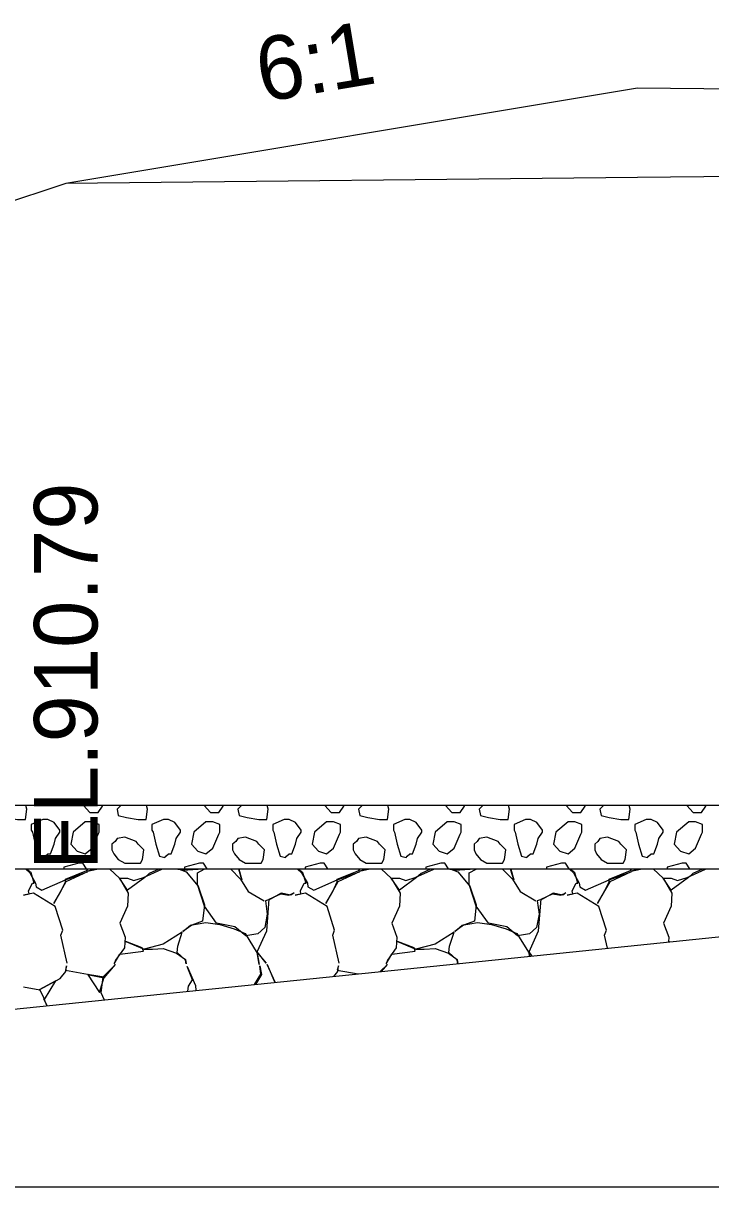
# Model space of a CAD drawing. Extents: x -26 to 4781, y -31 to 24738.
# Drawn here: x 2268.33 to 2279.16, y 7000 to 7018.31 of the extents above; entities that cross this region are included whole.
import ezdxf

# ---------------------------------------------------------------- set-up
doc = ezdxf.new("R2010")
doc.units = 0
for name, color, linetype in [('DESIGN - SHEET - Light Grid', 7, 'Continuous'), ('DESIGN - TRANSPORTATION - Proposed Layout Patterning', 7, 'Continuous'), ('DESIGN - TYPICAL - Finished Grade and Subgrade', 7, 'Continuous'), ('DESIGN - TYPICAL - Finished Grade Slopes Text', 7, 'Continuous'), ('DESIGN - TYPICAL - Subgrade Tie Text', 7, 'Continuous'), ('GEOTECHNICAL – SCRATCH – Level 1', 7, 'Continuous'), ('SURVEY - GROUND - Top of Ground', 7, 'Continuous')]:
    doc.layers.add(name, color=color, linetype=linetype)

msp = doc.modelspace()

# ---------------------------------------------------------------- linework, layer by layer
at = {"layer": 'DESIGN - SHEET - Light Grid'}
msp.add_line((2000, 7000), (2300, 7000), dxfattribs=at)
at = {"layer": 'DESIGN - TRANSPORTATION - Proposed Layout Patterning'}
for p, q in [((2269.308, 7005.741), (2269.118, 7005.581)), ((2271.208, 7005.741), (2271.018, 7005.581)), ((2273.108, 7005.741), (2272.918, 7005.581)), ((2275.008, 7005.741), (2274.818, 7005.581)), ((2276.908, 7005.741), (2276.718, 7005.581)), ((2278.808, 7005.741), (2278.618, 7005.581)), ((2268.458, 7005.611), (2268.478, 7005.581)), ((2270.358, 7005.611), (2270.378, 7005.581)), ((2272.258, 7005.611), (2272.278, 7005.581)), ((2274.158, 7005.611), (2274.178, 7005.581)), ((2276.058, 7005.611), (2276.078, 7005.581)), ((2277.958, 7005.611), (2277.978, 7005.581))]:
    msp.add_line(p, q, dxfattribs=at)
for points in [[(2267.967, 7006), (2267.908, 7005.941), (2267.928, 7005.841), (2268.058, 7005.811), (2268.238, 7005.781), (2268.368, 7005.781), (2268.388, 7005.941), (2268.371, 7006)], [(2269.279, 7006), (2269.378, 7005.891), (2269.508, 7005.891), (2269.578, 7005.991), (2269.582, 7006)], [(2269.867, 7006), (2269.808, 7005.941), (2269.828, 7005.841), (2269.958, 7005.811), (2270.138, 7005.781), (2270.268, 7005.781), (2270.288, 7005.941), (2270.271, 7006)], [(2271.179, 7006), (2271.278, 7005.891), (2271.408, 7005.891), (2271.478, 7005.991), (2271.482, 7006)], [(2271.767, 7006), (2271.708, 7005.941), (2271.728, 7005.841), (2271.858, 7005.811), (2272.038, 7005.781), (2272.168, 7005.781), (2272.188, 7005.941), (2272.171, 7006)], [(2273.079, 7006), (2273.178, 7005.891), (2273.308, 7005.891), (2273.378, 7005.991), (2273.382, 7006)], [(2273.667, 7006), (2273.608, 7005.941), (2273.628, 7005.841), (2273.758, 7005.811), (2273.938, 7005.781), (2274.068, 7005.781), (2274.088, 7005.941), (2274.071, 7006)], [(2274.979, 7006), (2275.078, 7005.891), (2275.208, 7005.891), (2275.278, 7005.991), (2275.282, 7006)], [(2275.567, 7006), (2275.508, 7005.941), (2275.528, 7005.841), (2275.658, 7005.811), (2275.838, 7005.781), (2275.968, 7005.781), (2275.988, 7005.941), (2275.971, 7006)], [(2276.879, 7006), (2276.978, 7005.891), (2277.108, 7005.891), (2277.178, 7005.991), (2277.182, 7006)], [(2277.467, 7006), (2277.408, 7005.941), (2277.428, 7005.841), (2277.558, 7005.811), (2277.738, 7005.781), (2277.868, 7005.781), (2277.888, 7005.941), (2277.871, 7006)], [(2278.779, 7006), (2278.878, 7005.891), (2279.008, 7005.891), (2279.078, 7005.991), (2279.082, 7006)], [(2268.718, 7005.781), (2268.658, 7005.781), (2268.638, 7005.781), (2268.458, 7005.701), (2268.458, 7005.611)], [(2268.908, 7005.581), (2268.908, 7005.611), (2268.818, 7005.731), (2268.718, 7005.781)], [(2269.528, 7005.581), (2269.528, 7005.701), (2269.418, 7005.741), (2269.308, 7005.741)], [(2270.618, 7005.781), (2270.558, 7005.781), (2270.538, 7005.781), (2270.358, 7005.701), (2270.358, 7005.611)], [(2270.808, 7005.581), (2270.808, 7005.611), (2270.718, 7005.731), (2270.618, 7005.781)], [(2271.428, 7005.581), (2271.428, 7005.701), (2271.318, 7005.741), (2271.208, 7005.741)], [(2272.518, 7005.781), (2272.458, 7005.781), (2272.438, 7005.781), (2272.258, 7005.701), (2272.258, 7005.611)], [(2272.708, 7005.581), (2272.708, 7005.611), (2272.618, 7005.731), (2272.518, 7005.781)], [(2273.328, 7005.581), (2273.328, 7005.701), (2273.218, 7005.741), (2273.108, 7005.741)], [(2274.418, 7005.781), (2274.358, 7005.781), (2274.338, 7005.781), (2274.158, 7005.701), (2274.158, 7005.611)], [(2274.608, 7005.581), (2274.608, 7005.611), (2274.518, 7005.731), (2274.418, 7005.781)], [(2275.228, 7005.581), (2275.228, 7005.701), (2275.118, 7005.741), (2275.008, 7005.741)], [(2276.318, 7005.781), (2276.258, 7005.781), (2276.238, 7005.781), (2276.058, 7005.701), (2276.058, 7005.611)], [(2276.508, 7005.581), (2276.508, 7005.611), (2276.418, 7005.731), (2276.318, 7005.781)], [(2277.128, 7005.581), (2277.128, 7005.701), (2277.018, 7005.741), (2276.908, 7005.741)], [(2278.218, 7005.781), (2278.158, 7005.781), (2278.138, 7005.781), (2277.958, 7005.701), (2277.958, 7005.611)], [(2278.408, 7005.581), (2278.408, 7005.611), (2278.318, 7005.731), (2278.218, 7005.781)], [(2279.028, 7005.581), (2279.028, 7005.701), (2278.918, 7005.741), (2278.808, 7005.741)], [(2268.478, 7005.581), (2268.518, 7005.391), (2268.578, 7005.201), (2268.658, 7005.181), (2268.678, 7005.201), (2268.718, 7005.241)], [(2268.718, 7005.241), (2268.758, 7005.241), (2268.818, 7005.391), (2268.838, 7005.481), (2268.908, 7005.581)], [(2269.118, 7005.581), (2269.078, 7005.391), (2269.178, 7005.281), (2269.308, 7005.241), (2269.418, 7005.331), (2269.508, 7005.551), (2269.528, 7005.581)], [(2270.378, 7005.581), (2270.418, 7005.391), (2270.478, 7005.201), (2270.558, 7005.181), (2270.578, 7005.201), (2270.618, 7005.241)], [(2270.618, 7005.241), (2270.658, 7005.241), (2270.718, 7005.391), (2270.738, 7005.481), (2270.808, 7005.581)], [(2271.018, 7005.581), (2270.978, 7005.391), (2271.078, 7005.281), (2271.208, 7005.241), (2271.318, 7005.331), (2271.408, 7005.551), (2271.428, 7005.581)], [(2272.278, 7005.581), (2272.318, 7005.391), (2272.378, 7005.201), (2272.458, 7005.181), (2272.478, 7005.201), (2272.518, 7005.241)], [(2272.518, 7005.241), (2272.558, 7005.241), (2272.618, 7005.391), (2272.638, 7005.481), (2272.708, 7005.581)], [(2272.918, 7005.581), (2272.878, 7005.391), (2272.978, 7005.281), (2273.108, 7005.241), (2273.218, 7005.331), (2273.308, 7005.551), (2273.328, 7005.581)], [(2274.178, 7005.581), (2274.218, 7005.391), (2274.278, 7005.201), (2274.358, 7005.181), (2274.378, 7005.201), (2274.418, 7005.241)], [(2274.418, 7005.241), (2274.458, 7005.241), (2274.518, 7005.391), (2274.538, 7005.481), (2274.608, 7005.581)], [(2274.818, 7005.581), (2274.778, 7005.391), (2274.878, 7005.281), (2275.008, 7005.241), (2275.118, 7005.331), (2275.208, 7005.551), (2275.228, 7005.581)], [(2276.078, 7005.581), (2276.118, 7005.391), (2276.178, 7005.201), (2276.258, 7005.181), (2276.278, 7005.201), (2276.318, 7005.241)], [(2276.318, 7005.241), (2276.358, 7005.241), (2276.418, 7005.391), (2276.438, 7005.481), (2276.508, 7005.581)], [(2276.718, 7005.581), (2276.678, 7005.391), (2276.778, 7005.281), (2276.908, 7005.241), (2277.018, 7005.331), (2277.108, 7005.551), (2277.128, 7005.581)], [(2277.978, 7005.581), (2278.018, 7005.391), (2278.078, 7005.201), (2278.158, 7005.181), (2278.178, 7005.201), (2278.218, 7005.241)], [(2278.218, 7005.241), (2278.258, 7005.241), (2278.318, 7005.391), (2278.338, 7005.481), (2278.408, 7005.581)], [(2278.618, 7005.581), (2278.578, 7005.391), (2278.678, 7005.281), (2278.808, 7005.241), (2278.918, 7005.331), (2279.008, 7005.551), (2279.028, 7005.581)], [(2270.108, 7005.431), (2269.928, 7005.501), (2269.808, 7005.481), (2269.778, 7005.431), (2269.728, 7005.391), (2269.728, 7005.301), (2269.758, 7005.241), (2269.828, 7005.151), (2269.928, 7005.091), (2270.058, 7005.091), (2270.178, 7005.091), (2270.208, 7005.151), (2270.228, 7005.301), (2270.138, 7005.391), (2270.108, 7005.431)], [(2272.008, 7005.431), (2271.828, 7005.501), (2271.708, 7005.481), (2271.678, 7005.431), (2271.628, 7005.391), (2271.628, 7005.301), (2271.658, 7005.241), (2271.728, 7005.151), (2271.828, 7005.091), (2271.958, 7005.091), (2272.078, 7005.091), (2272.108, 7005.151), (2272.128, 7005.301), (2272.038, 7005.391), (2272.008, 7005.431)], [(2273.908, 7005.431), (2273.728, 7005.501), (2273.608, 7005.481), (2273.578, 7005.431), (2273.528, 7005.391), (2273.528, 7005.301), (2273.558, 7005.241), (2273.628, 7005.151), (2273.728, 7005.091), (2273.858, 7005.091), (2273.978, 7005.091), (2274.008, 7005.151), (2274.028, 7005.301), (2273.938, 7005.391), (2273.908, 7005.431)], [(2275.808, 7005.431), (2275.628, 7005.501), (2275.508, 7005.481), (2275.478, 7005.431), (2275.428, 7005.391), (2275.428, 7005.301), (2275.458, 7005.241), (2275.528, 7005.151), (2275.628, 7005.091), (2275.758, 7005.091), (2275.878, 7005.091), (2275.908, 7005.151), (2275.928, 7005.301), (2275.838, 7005.391), (2275.808, 7005.431)], [(2277.708, 7005.431), (2277.528, 7005.501), (2277.408, 7005.481), (2277.378, 7005.431), (2277.328, 7005.391), (2277.328, 7005.301), (2277.358, 7005.241), (2277.428, 7005.151), (2277.528, 7005.091), (2277.658, 7005.091), (2277.778, 7005.091), (2277.808, 7005.151), (2277.828, 7005.301), (2277.738, 7005.391), (2277.708, 7005.431)], [(2269.024, 7003.518), (2268.924, 7003.958), (2268.954, 7004.038), (2268.834, 7004.408), (2268.494, 7004.618), (2268.334, 7004.588), (2268.424, 7004.608), (2268.414, 7004.658), (2268.474, 7004.778), (2268.504, 7004.778), (2268.454, 7004.938), (2268.38, 7005)], [(2268.371, 7005), (2268.434, 7004.938), (2268.524, 7004.778), (2268.534, 7004.718), (2268.624, 7004.668), (2268.994, 7004.828), (2269.344, 7004.958), (2269.004, 7004.798), (2268.924, 7004.658), (2268.814, 7004.458), (2268.924, 7004.648), (2268.994, 7004.798), (2268.994, 7004.838), (2269.334, 7004.978), (2269.349, 7005)], [(2269.208, 7005.091), (2268.968, 7005.031), (2268.968, 7005)], [(2269.329, 7005), (2269.328, 7005.001), (2269.268, 7005.091), (2269.208, 7005.091)], [(2269.465, 7005), (2269.344, 7004.968), (2269.488, 7005)], [(2269.693, 7005), (2269.844, 7004.858), (2269.984, 7004.618), (2269.974, 7004.418), (2269.854, 7004.148), (2269.934, 7003.928), (2269.924, 7003.758), (2269.784, 7003.568), (2269.764, 7003.508), (2269.854, 7003.658), (2270.224, 7003.708), (2270.204, 7003.758), (2269.944, 7003.858), (2270.234, 7003.738), (2270.364, 7003.738), (2270.534, 7003.748), (2270.744, 7003.678), (2270.884, 7003.578), (2270.894, 7003.508), (2270.884, 7003.568), (2270.754, 7003.688), (2270.764, 7003.788), (2270.834, 7004.008), (2270.534, 7003.818), (2270.234, 7003.738)], [(2270.465, 7005), (2270.314, 7004.928), (2270.244, 7004.868), (2269.974, 7004.668), (2269.844, 7004.858), (2269.974, 7004.858), (2270.074, 7004.818), (2270.224, 7004.868), (2270.514, 7005)], [(2270.766, 7005), (2270.784, 7004.998), (2270.894, 7004.958), (2271.084, 7004.728), (2271.184, 7004.438), (2271.154, 7004.178), (2270.984, 7004.118), (2270.844, 7004.018), (2270.964, 7004.118), (2271.204, 7004.158), (2271.424, 7004.128), (2271.654, 7004.058), (2271.824, 7003.988), (2272.014, 7003.678), (2272.044, 7003.498), (2272.014, 7003.688), (2272.154, 7003.518), (2272.014, 7003.698), (2272.164, 7004.028), (2272.204, 7004.528), (2272.384, 7004.608), (2272.514, 7004.588), (2272.594, 7004.628), (2272.544, 7004.588), (2272.394, 7004.618), (2272.224, 7004.528), (2272.144, 7004.498), (2272.174, 7004.288), (2272.134, 7004.078), (2272.024, 7003.978), (2271.834, 7003.948), (2271.664, 7004.088), (2271.374, 7004.148), (2271.184, 7004.418), (2271.074, 7004.758), (2271.074, 7004.938), (2271.181, 7005)], [(2271.168, 7005), (2271.164, 7004.998), (2270.844, 7004.978), (2270.833, 7005)], [(2271.108, 7005.091), (2270.868, 7005.031), (2270.868, 7005)], [(2271.229, 7005), (2271.228, 7005.001), (2271.168, 7005.091), (2271.108, 7005.091)], [(2271.598, 7005), (2271.754, 7004.838), (2271.874, 7004.648), (2272.124, 7004.498)], [(2271.727, 7005), (2271.774, 7004.828), (2271.725, 7005)], [(2273.304, 7003.518), (2273.204, 7003.958), (2273.234, 7004.038), (2273.114, 7004.408), (2272.774, 7004.618), (2272.614, 7004.588), (2272.704, 7004.608), (2272.694, 7004.658), (2272.754, 7004.778), (2272.784, 7004.778), (2272.734, 7004.938), (2272.66, 7005)], [(2272.651, 7005), (2272.714, 7004.938), (2272.804, 7004.778), (2272.814, 7004.718), (2272.904, 7004.668), (2273.274, 7004.828), (2273.624, 7004.958), (2273.284, 7004.798), (2273.204, 7004.658), (2273.094, 7004.458), (2273.204, 7004.648), (2273.274, 7004.798), (2273.274, 7004.838), (2273.614, 7004.978), (2273.629, 7005)], [(2273.008, 7005.091), (2272.768, 7005.031), (2272.768, 7005)], [(2273.129, 7005), (2273.128, 7005.001), (2273.068, 7005.091), (2273.008, 7005.091)], [(2273.745, 7005), (2273.624, 7004.968), (2273.768, 7005)], [(2273.973, 7005), (2274.124, 7004.858), (2274.264, 7004.618), (2274.254, 7004.418), (2274.134, 7004.148), (2274.214, 7003.928), (2274.204, 7003.758), (2274.064, 7003.568), (2274.044, 7003.508), (2274.134, 7003.658), (2274.504, 7003.708), (2274.484, 7003.758), (2274.224, 7003.858), (2274.514, 7003.738), (2274.644, 7003.738), (2274.814, 7003.748), (2275.024, 7003.678), (2275.164, 7003.578), (2275.173, 7003.511)], [(2274.745, 7005), (2274.594, 7004.928), (2274.524, 7004.868), (2274.254, 7004.668), (2274.124, 7004.858), (2274.254, 7004.858), (2274.354, 7004.818), (2274.504, 7004.868), (2274.794, 7005)], [(2274.908, 7005.091), (2274.668, 7005.031), (2274.668, 7005)], [(2275.029, 7005), (2275.028, 7005.001), (2274.968, 7005.091), (2274.908, 7005.091)], [(2275.046, 7005), (2275.064, 7004.998), (2275.174, 7004.958), (2275.364, 7004.728), (2275.464, 7004.438), (2275.434, 7004.178), (2275.264, 7004.118), (2275.124, 7004.018), (2275.244, 7004.118), (2275.484, 7004.158), (2275.704, 7004.128), (2275.934, 7004.058), (2276.104, 7003.988), (2276.294, 7003.678), (2276.302, 7003.627)], [(2275.448, 7005), (2275.444, 7004.998), (2275.124, 7004.978), (2275.113, 7005)], [(2276.345, 7003.631), (2276.294, 7003.698), (2276.444, 7004.028), (2276.484, 7004.528), (2276.664, 7004.608), (2276.794, 7004.588), (2276.874, 7004.628), (2276.824, 7004.588), (2276.674, 7004.618), (2276.504, 7004.528), (2276.424, 7004.498), (2276.454, 7004.288), (2276.414, 7004.078), (2276.304, 7003.978), (2276.114, 7003.948), (2275.944, 7004.088), (2275.654, 7004.148), (2275.464, 7004.418), (2275.354, 7004.758), (2275.354, 7004.938), (2275.461, 7005)], [(2275.878, 7005), (2276.034, 7004.838), (2276.154, 7004.648), (2276.404, 7004.498)], [(2276.007, 7005), (2276.054, 7004.828), (2276.005, 7005)], [(2276.808, 7005.091), (2276.568, 7005.031), (2276.568, 7005)], [(2276.929, 7005), (2276.928, 7005.001), (2276.868, 7005.091), (2276.808, 7005.091)], [(2277.53, 7003.753), (2277.484, 7003.958), (2277.514, 7004.038), (2277.394, 7004.408), (2277.054, 7004.618), (2276.894, 7004.588), (2276.984, 7004.608), (2276.974, 7004.658), (2277.034, 7004.778), (2277.064, 7004.778), (2277.014, 7004.938), (2276.94, 7005)], [(2276.931, 7005), (2276.994, 7004.938), (2277.084, 7004.778), (2277.094, 7004.718), (2277.184, 7004.668), (2277.554, 7004.828), (2277.904, 7004.958), (2277.564, 7004.798), (2277.484, 7004.658), (2277.374, 7004.458), (2277.484, 7004.648), (2277.554, 7004.798), (2277.554, 7004.838), (2277.894, 7004.978), (2277.909, 7005)], [(2278.025, 7005), (2277.904, 7004.968), (2278.048, 7005)], [(2278.253, 7005), (2278.404, 7004.858), (2278.544, 7004.618), (2278.534, 7004.418), (2278.414, 7004.148), (2278.494, 7003.928), (2278.489, 7003.852)], [(2279.025, 7005), (2278.874, 7004.928), (2278.804, 7004.868), (2278.534, 7004.668), (2278.404, 7004.858), (2278.534, 7004.858), (2278.634, 7004.818), (2278.784, 7004.868), (2279.074, 7005)], [(2278.708, 7005.091), (2278.468, 7005.031), (2278.468, 7005)], [(2278.829, 7005), (2278.828, 7005.001), (2278.768, 7005.091), (2278.708, 7005.091)], [(2275.173, 7003.511), (2275.164, 7003.568), (2275.034, 7003.688), (2275.044, 7003.788), (2275.114, 7004.008), (2274.814, 7003.818), (2274.514, 7003.738)], [(2276.303, 7003.627), (2276.294, 7003.688), (2276.34, 7003.631)], [(2278.513, 7003.854), (2278.504, 7003.858), (2278.512, 7003.854)], [(2268.334, 7003.148), (2268.594, 7003.098), (2268.664, 7002.948), (2268.844, 7003.238), (2268.584, 7003.098), (2268.914, 7003.278), (2269.004, 7003.388), (2269.014, 7003.478), (2268.994, 7003.408), (2269.344, 7003.348), (2269.534, 7003.058), (2269.604, 7003.298), (2269.344, 7003.338), (2269.604, 7003.288), (2269.784, 7003.498), (2269.584, 7003.298), (2269.554, 7003.058), (2269.603, 7002.941)], [(2272.298, 7003.217), (2272.174, 7003.498), (2272.29, 7003.216)], [(2273.97, 7003.388), (2274.064, 7003.498), (2273.953, 7003.386)], [(2270.92, 7003.076), (2270.934, 7003.158), (2270.994, 7003.258), (2270.914, 7003.468), (2271.044, 7003.168), (2271.047, 7003.089)], [(2271.972, 7003.183), (2272.074, 7003.348), (2272.054, 7003.478), (2272.084, 7003.338), (2271.987, 7003.185)], [(2273.222, 7003.311), (2273.284, 7003.388), (2273.294, 7003.478), (2273.274, 7003.408), (2273.606, 7003.351)], [(2268.708, 7002.849), (2268.654, 7002.958), (2268.704, 7002.849)]]:
    msp.add_lwpolyline(points, dxfattribs=at)
at = {"layer": 'DESIGN - TYPICAL - Finished Grade and Subgrade'}
for p, q in [((2278, 7017.292), (2269, 7015.792)), ((2288, 7017.192), (2278, 7017.292)), ((2288, 7015.982), (2278, 7015.882)), ((2269, 7015.792), (2226.581, 7001.652)), ((2278, 7015.882), (2269, 7015.792))]:
    msp.add_line(p, q, dxfattribs=at)
at = {"layer": 'GEOTECHNICAL – SCRATCH – Level 1'}
for p, q in [((2299.066, 7006), (2239.625, 7006)), ((2290.193, 7005), (2236.625, 7005))]:
    msp.add_line(p, q, dxfattribs=at)
at = {"layer": 'SURVEY - GROUND - Top of Ground'}
msp.add_lwpolyline([(2221.065, 7001.486), (2231.615, 7001.803), (2234.076, 7001.953), (2237.012, 7001.948), (2244.332, 7002.031), (2247.669, 7002.206), (2252.499, 7002.233), (2256.305, 7002.33), (2264.092, 7002.523), (2265.59, 7002.579), (2265.997, 7002.593), (2266.436, 7002.617), (2275.198, 7003.514), (2281.873, 7004.199), (2282.526, 7004.285), (2284.656, 7004.477), (2294.223, 7005.381), (2295.439, 7005.523), (2297.025, 7005.728), (2300, 7006.124), (2307.639, 7007.141), (2311.611, 7007.768)], dxfattribs=at)

# ---------------------------------------------------------------- texts
at = {"layer": 'DESIGN - TYPICAL - Finished Grade Slopes Text'}
msp.add_text('6:1', height=1, rotation=9.4623, dxfattribs=at).set_placement((2272.088, 7017.067))
at = {"layer": 'DESIGN - TYPICAL - Subgrade Tie Text'}
msp.add_text('EL.910.79', height=1, rotation=90, dxfattribs=at).set_placement((2269.5, 7004.986))

doc.saveas('drawing.dxf')
